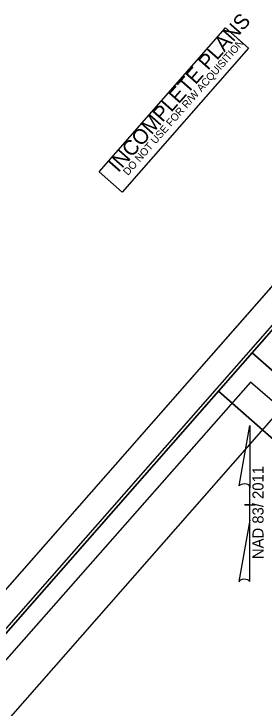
# Model space of a CAD drawing. Extents: x 2189835 to 2191772, y 387461 to 389531.
# Drawn here: x 2190636 to 2190829, y 388998 to 389531 of the extents above; entities that cross this region are included whole.
import ezdxf

# ---------------------------------------------------------------- set-up
doc = ezdxf.new("R2010")
doc.units = 0
for name, color, linetype in [('Prop North Arrow NAD83 for Plan Sheets CELL', 7, 'Continuous'), ('Sheet Clip Boundary CELL', 7, 'Continuous'), ('Sheet Cutting Line CELL', 7, 'Continuous'), ('Sheet Layout Plan Border', 7, 'Continuous'), ('Sheet Plan CELL', 7, 'Continuous'), ('Sheet Plan Layout CELL', 7, 'Continuous'), ('Sheet Plot Border Inside CELL', 7, 'Continuous'), ('Sheet Plot Border Outside CELL', 7, 'Continuous'), ('Sheet Sticker Incomplete CELL', 7, 'Continuous')]:
    doc.layers.add(name, color=color, linetype=linetype)

msp = doc.modelspace()

# ---------------------------------------------------------------- linework, layer by layer
at = {"layer": 'Prop North Arrow NAD83 for Plan Sheets CELL'}
for p, q in [((2190809.51, 389168.37), (2190817.71, 389214.72)), ((2190817.76, 389214.72), (2190817.71, 389214.72)), ((2190817.76, 389214.72), (2190817.71, 389214.72)), ((2190817.76, 389214.72), (2190817.76, 389166.92)), ((2190817.76, 389142.12), (2190817.76, 389168.32)), ((2190817.76, 389166.92), (2190817.76, 389168.27)), ((2190813.76, 389153.72), (2190813.71, 389153.72)), ((2190817.31, 389153.72), (2190813.76, 389153.72)), ((2190813.81, 389153.72), (2190821.81, 389153.72)), ((2190817.76, 389142.12), (2190809.41, 389094.87)), ((2190817.81, 389095.07), (2190817.76, 389142.12))]:
    msp.add_line(p, q, dxfattribs=at)
for centre, start_param, end_param in [((2190813.65, 389167.87), 0.216388, 2.908219), ((2190813.65, 389094.7), 0.201328, 3.141593)]:
    msp.add_ellipse(centre, major_axis=(4.23, -0.03), ratio=0.461098, start_param=start_param, end_param=end_param, dxfattribs=at)
at = {"layer": 'Sheet Clip Boundary CELL'}
msp.add_lwpolyline([(2190233.88, 388250.3), (2190718.45, 387881.26), (2190850.4, 387777.99), (2191678.63, 388725.5), (2191058.62, 389246.4), (2190957.74, 389128.02), (2190818.15, 389247.91), (2190051.03, 388378.47)], close=True, dxfattribs=at)
at = {"layer": 'Sheet Cutting Line CELL'}
msp.add_line((2190946.11, 389448.37), (2189834.54, 388184.02), dxfattribs=at)
at = {"layer": 'Sheet Layout Plan Border'}
msp.add_lwpolyline([(2190847.19, 387643.49), (2191771.58, 388694.94), (2191141.84, 389248.59), (2191016.87, 389106.45), (2190858.04, 389246.09), (2190058.62, 388336.78)], close=True, dxfattribs=at)
at = {"layer": 'Sheet Plan CELL'}
for points in [[(2190951.79, 389420.78), (2189961.36, 388294.21), (2190749.93, 387600.92), (2191740.35, 388727.47)], [(2190819.67, 389270.52), (2190951.79, 389420.78), (2190970.58, 389404.21), (2190838.52, 389253.96)], [(2190749.93, 387600.92), (2189961.36, 388294.17), (2190819.67, 389270.52), (2190932.38, 389171.45), (2191064.47, 389321.68), (2191740.35, 388727.47)]]:
    msp.add_lwpolyline(points, close=True, dxfattribs=at)
at = {"layer": 'Sheet Plan Layout CELL'}
for points in [[(2190952.63, 389101.43), (2191110.61, 389281.13), (2190951.8, 389420.79), (2190793.79, 389241.07)], [(2189961.36, 388294.17), (2190749.93, 387600.92), (2191740.34, 388727.46), (2191110.6, 389281.11), (2190952.63, 389101.43), (2190793.79, 389241.07)]]:
    msp.add_lwpolyline(points, close=True, dxfattribs=at)
at = {"layer": 'Sheet Plot Border Inside CELL'}
msp.add_lwpolyline([(2190650.48, 387483.99), (2191750.47, 388735.2), (2190958.16, 389431.79), (2189858.14, 388180.58)], close=True, dxfattribs=at)
at = {"layer": 'Sheet Plot Border Outside CELL'}
msp.add_lwpolyline([(2190656.91, 387461.02), (2191768.48, 388725.38), (2190946.11, 389448.37), (2189834.54, 388184.02)], close=True, dxfattribs=at)
at = {"layer": 'Sheet Sticker Incomplete CELL'}
msp.add_lwpolyline([(2190719.61, 389393.85), (2190701.96, 389409.37), (2190799.02, 389519.77), (2190816.67, 389504.25)], close=True, dxfattribs=at)

# ---------------------------------------------------------------- texts
at = {"layer": 'Prop North Arrow NAD83 for Plan Sheets CELL'}
msp.add_text('NAD 83/ 2011', height=8.5, rotation=90, dxfattribs=at).set_placement((2190828.28, 389112.2))
at = {"layer": 'Sheet Sticker Incomplete CELL'}
for s, height, p in [('INCOMPLETE PLANS', 11.52, (2190716.73, 389408.3)), ('DO NOT USE FOR R/W ACQUISITION', 5.76, (2190724.09, 389406.15))]:
    msp.add_text(s, height=height, rotation=48.6794, dxfattribs=at).set_placement(p)

doc.saveas('drawing.dxf')
